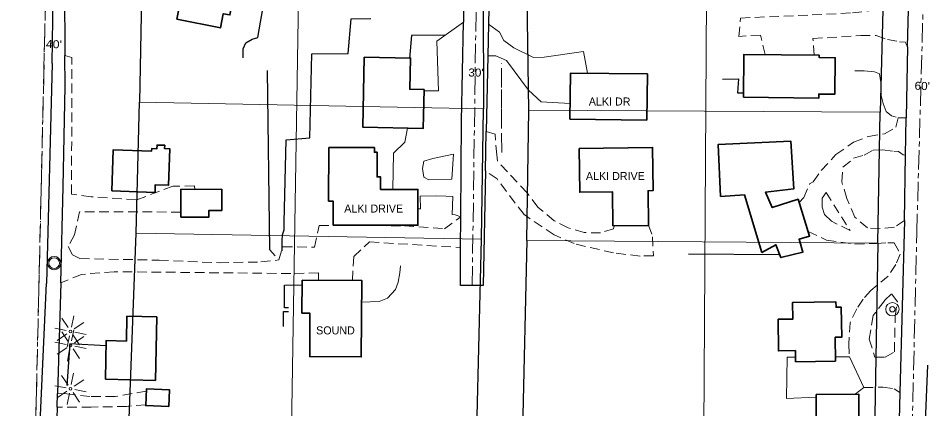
# Model space of a CAD drawing. Extents: x -861682 to -858969, y -1797841 to -1795153.
# Drawn here: x -861677 to -860995, y -1797216 to -1796923 of the extents above; entities that cross this region are included whole.
import ezdxf

# ---------------------------------------------------------------- set-up
doc = ezdxf.new("R2010")
doc.units = 0
doc.header["$LTSCALE"] = 2.4
for name, pattern in [('DOT_DASHED', [7.7, 5, -1.2, 0.3, -1.2]), ('LONG_DASH_SHORT_DASH', [9.9, 6, -1.2, 1.5, -1.2]), ('LONG_DASHED', [7.5, 6, -1.5]), ('MEDIUM_DASHED', [4.5, 3, -1.5])]:
    doc.linetypes.add(name, pattern=pattern)
for name, color, linetype, lineweight in [('10', 7, 'Continuous', 25), ('11', 7, 'Continuous', 13), ('12', 7, 'Continuous', 35), ('14', 7, 'Continuous', 25), ('17', 7, 'Continuous', 13), ('30', 7, 'Continuous', 13), ('31', 7, 'Continuous', 13), ('32', 7, 'LONG_DASH_SHORT_DASH', 13), ('36', 7, 'Continuous', 13), ('42', 7, 'Continuous', 25), ('46', 7, 'Continuous', 13), ('52', 7, 'LONG_DASHED', 13), ('61', 7, 'Continuous', 13)]:
    doc.layers.add(name, color=color, linetype=linetype, lineweight=lineweight)
doc.layers.add('43', color=7, linetype='Continuous')

msp = doc.modelspace()

# ---------------------------------------------------------------- linework, layer by layer
at = {"layer": '10'}
for p, q in [((-861010.143, -1796944.779), (-861009.05, -1796903.728)), ((-861323.862, -1796916.281), (-861324.107, -1796927.841)), ((-861010.143, -1796944.779), (-861010.99, -1796997.92)), ((-861011.439, -1797026.06), (-861010.99, -1796997.92)), ((-861326.432, -1797037.668), (-861325.808, -1797008.224)), ((-861012.218, -1797074.91), (-861011.439, -1797026.06)), ((-861345.039, -1797095.137), (-861344.865, -1797072)), ((-861012.218, -1797074.91), (-861015.76, -1797203.66)), ((-861644.853, -1797121.521), (-861647.128, -1797204.461)), ((-860998.692, -1797277.689), (-860994.825, -1797183.063)), ((-861647.407, -1797214.598), (-861647.128, -1797204.461)), ((-861647.407, -1797214.598), (-861649.011, -1797273.028))]:
    msp.add_line(p, q, dxfattribs=at)
for points in [[(-861342.201, -1796882.821), (-861342.913, -1796922.043), (-861342.989, -1796926.297)], [(-861641.79, -1796888.674), (-861642.058, -1796901.266), (-861641.695, -1796951.331)], [(-861344.865, -1797072), (-861344.329, -1797000.201), (-861342.989, -1796926.297)], [(-861324.107, -1796927.841), (-861324.612, -1796951.71), (-861325.808, -1797008.224)], [(-861644.853, -1797121.521), (-861642.88, -1797049.578), (-861641.529, -1796974.238), (-861641.695, -1796951.331)], [(-861326.432, -1797037.668), (-861328.248, -1797123.413), (-861345.252, -1797123.481), (-861345.039, -1797095.137)], [(-861015.76, -1797203.66), (-861017.164, -1797254.647), (-861017.272, -1797257.025)]]:
    msp.add_lwpolyline(points, dxfattribs=at)
at = {"layer": '11'}
for p, q in [((-861063.645, -1797177.024), (-861053.617, -1797176.953)), ((-861042.889, -1797199.962), (-861053.617, -1797176.953)), ((-861049.334, -1797204.944), (-861042.889, -1797199.962))]:
    msp.add_line(p, q, dxfattribs=at)
at = {"layer": '11', "linetype": 'MEDIUM_DASHED'}
for points in [[(-861116.694, -1796950.677), (-861120.23, -1796936.01), (-861136.522, -1796937.02), (-861135.16, -1796923.317), (-861081.56, -1796920.977), (-861051.337, -1796919.439), (-861031.509, -1796916.998), (-861019.483, -1796912.462), (-861011.719, -1796905.11), (-861009.05, -1796903.728)], [(-861079.929, -1796951.135), (-861081.017, -1796938.687), (-861045.129, -1796936.418), (-861033.557, -1796936.371), (-861025.043, -1796939.407), (-861016.062, -1796941.025), (-861011.809, -1796941.479), (-861010.143, -1796944.779)], [(-861544.283, -1797051.544), (-861544.638, -1797048.949), (-861560.696, -1797049.249), (-861588.286, -1797059.515), (-861622.067, -1797057.052), (-861636.717, -1797055.222), (-861636.419, -1796952.963), (-861641.695, -1796951.331)], [(-861091.353, -1797061.34), (-861087.859, -1797057.738), (-861083.414, -1797047.329), (-861080.822, -1797045.902), (-861074.716, -1797037.375), (-861063.664, -1797025.523), (-861050.476, -1797016.26), (-861039.394, -1797011.965), (-861027.357, -1797010.028), (-861018.875, -1797005.034), (-861017.014, -1796997.942), (-861010.99, -1796997.92)], [(-861229.902, -1797078.821), (-861230.409, -1797080.981), (-861240.079, -1797084.09), (-861252.36, -1797083.903), (-861264.419, -1797080.41), (-861274.832, -1797075.02), (-861287.153, -1797064.915), (-861295.226, -1797054.084), (-861317.284, -1797030.557), (-861318.013, -1797025.601), (-861319.255, -1797010.255), (-861325.808, -1797008.224)], [(-861012.218, -1797074.91), (-861019.755, -1797079.9), (-861030.615, -1797080.888), (-861040.063, -1797080.454), (-861049.541, -1797072.462), (-861055.502, -1797058.316), (-861059.331, -1797045.815), (-861058.43, -1797034.948), (-861050.427, -1797028.303), (-861042.643, -1797025.911), (-861035.809, -1797022.341), (-861028.489, -1797022.075), (-861020.219, -1797022.987), (-861016.913, -1797023.21), (-861013.36, -1797025.794), (-861011.439, -1797026.06)], [(-861204.222, -1797078.316), (-861201.1, -1797087.004), (-861200.57, -1797101.408), (-861210.489, -1797101.447), (-861230.336, -1797099.165), (-861259.885, -1797092.2), (-861275.025, -1797085.648), (-861297.523, -1797070.389), (-861317.704, -1797043.784), (-861326.432, -1797037.668)], [(-861554.714, -1797068.522), (-861630.76, -1797068.423), (-861634.469, -1797085.678), (-861639.157, -1797094.434), (-861636.063, -1797100.562), (-861630.384, -1797103.373), (-861571.102, -1797104.552), (-861525.986, -1797106.496), (-861494.815, -1797105.898), (-861481.359, -1797104.427), (-861478.329, -1797094.496), (-861454.475, -1797094.873), (-861450.998, -1797078.564), (-861387.232, -1797078.779), (-861357.23, -1797081.02), (-861344.865, -1797072)], [(-861084.575, -1797083.06), (-861070.728, -1797089.551), (-861049.461, -1797092.536), (-861033.404, -1797092), (-861024.904, -1797091.493), (-861019.945, -1797091.473), (-861015.424, -1797099.957), (-861018.699, -1797107.763), (-861024.568, -1797116.524), (-861037.514, -1797127.204), (-861043.391, -1797133.84), (-861048.086, -1797140.943), (-861053.004, -1797151.354), (-861054.12, -1797167.417), (-861053.617, -1797176.953)], [(-861426.134, -1797119.717), (-861425.163, -1797101.84), (-861413.398, -1797090.93), (-861345.039, -1797095.137)], [(-861451.478, -1797119.55), (-861451.564, -1797113.99), (-861472.344, -1797114.546), (-861604.839, -1797113.19), (-861629.155, -1797115.176), (-861644.853, -1797121.521)], [(-861042.889, -1797199.962), (-861028.485, -1797199.668), (-861019.978, -1797200.815), (-861015.76, -1797203.66)], [(-861580.652, -1797202.613), (-861603.991, -1797206.706), (-861622.885, -1797206.546), (-861640.132, -1797204.726), (-861647.128, -1797204.461)], [(-861581.028, -1797212.742), (-861595.224, -1797213.992), (-861621.908, -1797214.572), (-861647.407, -1797214.598)]]:
    msp.add_lwpolyline(points, dxfattribs=at)
at = {"layer": '11'}
for points in [[(-861372.503, -1796977.879), (-861361.659, -1796977.836), (-861362.753, -1796940.526), (-861342.989, -1796926.297)], [(-861249.861, -1796964.618), (-861252.905, -1796948.35), (-861282.408, -1796952.72), (-861290.437, -1796952.752), (-861305.108, -1796945.726), (-861312.688, -1796940.089), (-861316.019, -1796933.962), (-861324.107, -1796927.841)], [(-861262.947, -1796987.215), (-861284.636, -1796986.027), (-861294.117, -1796977.327), (-861310.738, -1796955.196), (-861318.546, -1796951.685), (-861324.612, -1796951.71)], [(-861384.884, -1797005.756), (-861386.774, -1797016.194), (-861395.479, -1797024.494), (-861395.981, -1797051.553)], [(-861377.058, -1797066.221), (-861375.238, -1797066.214), (-861375.277, -1797056.532), (-861363.233, -1797056.483), (-861355.911, -1797056.69), (-861350.95, -1797056.907), (-861351.369, -1797070.37), (-861349.242, -1797070.597), (-861344.865, -1797072)], [(-861094.016, -1797177.239), (-861100.368, -1797177.284), (-861100.716, -1797208.223), (-861078.52, -1797206.998)]]:
    msp.add_lwpolyline(points, dxfattribs=at)
msp.add_lwpolyline([(-861350.369, -1797025.259), (-861365.943, -1797028.391), (-861372.547, -1797030.543), (-861373.706, -1797035.98), (-861372.736, -1797042.352), (-861368.949, -1797044.462), (-861351.711, -1797043.921)], close=True, dxfattribs=at)
at = {"layer": '11', "linetype": 'MEDIUM_DASHED'}
for points in [[(-861067.006, -1797075.366), (-861072.221, -1797070.427), (-861073.897, -1797064.766), (-861073.923, -1797058.153), (-861071.106, -1797053.891), (-861053.044, -1797082.395)], [(-861027.327, -1797134.955), (-861035.784, -1797146.089), (-861038.784, -1797163.577), (-861034.479, -1797177.257), (-861026.685, -1797177.226), (-861019.853, -1797173.184), (-861019.25, -1797146.731), (-861017.641, -1797135.861), (-861022.152, -1797129.739)]]:
    msp.add_lwpolyline(points, close=True, dxfattribs=at)
at = {"layer": '12'}
for points in [[(-861557.655, -1796924.07), (-861525.038, -1796930.551), (-861522.953, -1796920.056), (-861518.03, -1796921.034), (-861514.896, -1796905.256), (-861518.03, -1796904.633), (-861515.701, -1796892.917), (-861534.817, -1796889.117), (-861535.959, -1796894.86), (-861541.116, -1796893.835), (-861542.194, -1796899.257), (-861546.355, -1796898.43), (-861549.481, -1796914.158), (-861555.449, -1796912.972)], [(-861417.258, -1796952.551), (-861418.464, -1797004.984), (-861373.15, -1797006.026), (-861372.481, -1796976.921), (-861383.145, -1796976.676), (-861382.609, -1796953.347)], [(-861133.031, -1796982.582), (-861076.586, -1796983.302), (-861076.547, -1796980.229), (-861064.557, -1796980.381), (-861064.21, -1796953.023), (-861076.231, -1796952.871), (-861076.21, -1796951.181), (-861132.632, -1796950.479)], [(-861263.092, -1796998.927), (-861205.465, -1796999.641), (-861205.038, -1796965.173), (-861262.665, -1796964.459)], [(-861119.339, -1797098.718), (-861132.265, -1797055.552), (-861150.209, -1797056.805), (-861152.017, -1797018.082), (-861097.474, -1797015.501), (-861095.205, -1797051.153), (-861116.45, -1797053.6), (-861111.445, -1797065.152), (-861092.104, -1797058.934), (-861083.492, -1797086.53), (-861091.275, -1797088.923), (-861088.403, -1797098.594), (-861104.918, -1797102.675), (-861108.735, -1797093.008)], [(-861606.497, -1797052.738), (-861574.139, -1797053.789), (-861573.955, -1797048.128), (-861564.018, -1797048.451), (-861563.132, -1797021.19), (-861566.945, -1797021.066), (-861566.864, -1797018.575), (-861572.619, -1797018.388), (-861572.71, -1797021.189), (-861576.626, -1797021.062), (-861576.685, -1797022.868), (-861605.491, -1797021.927)], [(-861443.909, -1797020.201), (-861443.984, -1797060.349), (-861440.678, -1797060.355), (-861440.711, -1797078.287), (-861377.081, -1797078.404), (-861377.032, -1797051.588), (-861405.056, -1797051.537), (-861405.039, -1797042.242), (-861407.688, -1797042.237), (-861407.653, -1797023.834), (-861409.651, -1797023.83), (-861409.643, -1797020.274)], [(-861256.154, -1797020.861), (-861201.131, -1797020.168), (-861200.724, -1797052.507), (-861204.546, -1797052.555), (-861204.22, -1797078.499), (-861230.885, -1797078.834), (-861231.205, -1797053.348), (-861255.742, -1797053.656)], [(-861554.698, -1797072.367), (-861533.68, -1797072.283), (-861533.7, -1797067.324), (-861524.018, -1797067.285), (-861524.082, -1797051.462), (-861554.782, -1797051.586)], [(-861463.821, -1797119.469), (-861419.185, -1797119.763), (-861419.561, -1797176.924), (-861458.176, -1797176.67), (-861457.963, -1797144.246), (-861463.983, -1797144.207)], [(-861063.986, -1797180.207), (-861093.977, -1797180.564), (-861094.075, -1797172.295), (-861106.765, -1797172.445), (-861107.045, -1797148.737), (-861095.993, -1797148.606), (-861096.14, -1797136.174), (-861063.69, -1797135.79), (-861063.642, -1797139.822), (-861059.661, -1797139.775), (-861059.396, -1797162.235), (-861064.199, -1797162.292)], [(-861611.363, -1797193.745), (-861573.81, -1797194.539), (-861572.806, -1797147.072), (-861595.237, -1797146.598), (-861595.628, -1797165.113), (-861610.752, -1797164.794)], [(-861563.813, -1797214.101), (-861581.055, -1797213.461), (-861580.591, -1797200.957), (-861563.349, -1797201.597)], [(-861078.528, -1797205.062), (-861046.411, -1797204.933), (-861046.275, -1797238.704), (-861078.392, -1797238.834)]]:
    msp.add_lwpolyline(points, close=True, dxfattribs=at)
at = {"layer": '14'}
msp.add_line((-861174.125, -1797099.883), (-861106.581, -1797100.321), dxfattribs=at)
for points in [[(-861507.944, -1796953.155), (-861507.972, -1796946.307), (-861506.101, -1796941.812), (-861501.388, -1796939.196), (-861497.143, -1796937.762), (-861488.6, -1796889.078), (-861485.53, -1796889.066), (-861483.64, -1796889.058)], [(-861478.789, -1797097.568), (-861478.79, -1797097.332), (-861478.819, -1797090.011), (-861478.601, -1797085.523), (-861477.435, -1797081.976), (-861477.222, -1797076.071), (-861475.816, -1797014.428), (-861458.11, -1797012.94), (-861456.472, -1796950.114), (-861429.315, -1796949.768), (-861427.057, -1796923.782), (-861412.415, -1796923.723)], [(-861356.866, -1796936.252), (-861381.899, -1796936.352), (-861383.483, -1796953.599)], [(-861483.969, -1797101.368), (-861488.002, -1797096.897), (-861489.722, -1796962.528)], [(-861148.673, -1796968.949), (-861136.629, -1796968.901), (-861137.532, -1796979.295), (-861132.989, -1796979.234)], [(-861474.13, -1797140.294), (-861476.964, -1797140.306), (-861477.032, -1797123.302), (-861463.844, -1797122.931)], [(-861477.853, -1797154.243), (-861477.898, -1797142.907), (-861474.12, -1797142.892)], [(-861610.835, -1797168.745), (-861637.921, -1797167.167), (-861640.158, -1797198.349)]]:
    msp.add_lwpolyline(points, dxfattribs=at)
at = {"layer": '17'}
for p, q in [((-861639.285, -1797155.055), (-861644.075, -1797147.927)), ((-861636.825, -1797154.595), (-861635.099, -1797146.195)), ((-861634.625, -1797155.995), (-861627.529, -1797151.255)), ((-861640.785, -1797157.255), (-861649.247, -1797155.581)), ((-861639.244, -1797165.446), (-861644.034, -1797158.318)), ((-861636.784, -1797164.986), (-861635.058, -1797156.586)), ((-861634.185, -1797158.515), (-861625.705, -1797160.239)), ((-861640.744, -1797167.646), (-861649.206, -1797165.972)), ((-861640.245, -1797159.755), (-861647.471, -1797164.611)), ((-861639.865, -1797169.715), (-861638.185, -1797161.115)), ((-861635.525, -1797160.655), (-861630.725, -1797167.869)), ((-861634.584, -1797166.386), (-861627.488, -1797161.646)), ((-861640.204, -1797170.146), (-861647.43, -1797175.002)), ((-861639.824, -1797180.106), (-861638.144, -1797171.506)), ((-861635.484, -1797171.046), (-861630.684, -1797178.26)), ((-861634.144, -1797168.906), (-861625.664, -1797170.63)), ((-861639.349, -1797198.037), (-861644.139, -1797190.909)), ((-861636.889, -1797197.577), (-861635.163, -1797189.177)), ((-861640.849, -1797200.237), (-861649.311, -1797198.563)), ((-861634.689, -1797198.977), (-861627.593, -1797194.237)), ((-861640.309, -1797202.737), (-861647.535, -1797207.593)), ((-861639.929, -1797212.697), (-861638.249, -1797204.097)), ((-861635.589, -1797203.637), (-861630.789, -1797210.851)), ((-861634.249, -1797201.497), (-861625.769, -1797203.221))]:
    msp.add_line(p, q, dxfattribs=at)
for centre in [(-861637.485, -1797157.955), (-861637.444, -1797168.346), (-861637.549, -1797200.937)]:
    msp.add_circle(centre, 1, dxfattribs=at)
at = {"layer": '30'}
for p, q in [((-861163.628, -1797374.823), (-861160.072, -1796802.305)), ((-861465.508, -1796850.044), (-861480.985, -1797800.155)), ((-861327.8, -1796991.251), (-861585.789, -1796986.257)), ((-861293.837, -1796992.387), (-861030.52, -1796993.813)), ((-861329.456, -1797088.773), (-861588.243, -1797084.303)), ((-861295.45, -1797089.904), (-861032.296, -1797091.766))]:
    msp.add_line(p, q, dxfattribs=at)
at = {"layer": '31'}
for radius in [5, 2]:
    msp.add_circle((-861021.398, -1797141.308), radius, dxfattribs=at)
at = {"layer": '32'}
for points in [[(-861016.908, -1797697.112), (-861016.908, -1797629.868), (-861015.071, -1797572.938), (-861015.071, -1797447.139), (-861012.317, -1797374.599), (-861007.726, -1797281.857), (-861003.087, -1797084.148), (-860992.207, -1796696.344), (-860992.984, -1796576.661), (-860989.487, -1796449.983), (-860987.933, -1796343.901), (-860987.544, -1796199.737), (-860984.047, -1796080.831), (-860987.933, -1795887.705), (-860991.735, -1795769.455)], [(-861635.972, -1796031.868), (-861668.34, -1797434.932), (-861671.877, -1797797.365)], [(-861336.345, -1797123.445), (-861333.081, -1796888.015), (-861331.83, -1796872.168), (-861327.659, -1796856.738), (-861321.821, -1796845.478), (-861312.646, -1796834.219), (-861305.557, -1796827.129), (-861293.463, -1796820.457), (-861279.702, -1796815.453), (-861249.874, -1796808.735), (-861088.25, -1796770.144), (-860993.655, -1796747.958)]]:
    msp.add_lwpolyline(points, dxfattribs=at)
at = {"layer": '36'}
for radius in [5, 4]:
    msp.add_circle((-861649.735, -1797106.757), radius, dxfattribs=at)
at = {"layer": '42'}
for p, q in [((-861651.202, -1796957.407), (-861647.476, -1796719.081)), ((-861328.727, -1796817.832), (-861327.8, -1796991.251)), ((-861583.726, -1796880.798), (-861585.789, -1796986.257)), ((-861651.202, -1796957.407), (-861655.483, -1797122.019)), ((-861588.243, -1797084.303), (-861585.789, -1796986.257)), ((-861329.456, -1797088.773), (-861327.8, -1796991.251)), ((-861295.45, -1797089.904), (-861293.837, -1796992.387)), ((-861032.296, -1797091.766), (-861030.52, -1796993.813)), ((-861593.747, -1797229.638), (-861588.243, -1797084.303)), ((-861332.881, -1797234.296), (-861329.456, -1797088.773)), ((-861295.45, -1797089.904), (-861298.67, -1797233.588)), ((-861662.023, -1797266.955), (-861655.483, -1797122.019))]:
    msp.add_line(p, q, dxfattribs=at)
for points in [[(-861293.837, -1796992.387), (-861296.182, -1796840.974), (-861024.656, -1796763.832), (-861030.52, -1796993.813)], [(-861032.296, -1797091.766), (-861034.85, -1797234.814), (-861037.376, -1797375.712)]]:
    msp.add_lwpolyline(points, dxfattribs=at)
at = {"layer": '52'}
for points in [[(-861314.241, -1797023.932), (-861314.372, -1796991.106), (-861314.436, -1796975.284), (-861314.509, -1796957.1)], [(-861018.669, -1796997.476), (-861021.979, -1796996.545), (-861026.007, -1796993.254), (-861028.392, -1796987.36), (-861029.834, -1796981.226), (-861030.109, -1796971.544), (-861031.079, -1796965.172), (-861034.864, -1796963.534), (-861042.424, -1796962.856), (-861049.509, -1796962.884)], [(-861419.292, -1797136.103), (-861406.134, -1797135.535), (-861399.768, -1797132.911), (-861393.89, -1797126.511), (-861391.786, -1797121.071), (-861390.634, -1797113.982), (-861390.182, -1797108.784)]]:
    msp.add_lwpolyline(points, dxfattribs=at)
at = {"layer": '61', "linetype": 'DOT_DASHED'}
msp.add_line((-861615.801, -1795157.51), (-861676.699, -1797797.295), dxfattribs=at)

# ---------------------------------------------------------------- texts
at = {"layer": '43'}
for s, rotation, width, p in [("40'", 358.633, 1.15, (-861656.023, -1796945.727)), ("30'", 359.193, 1.1, (-861339.335, -1796967.041)), ("60'", 358.37, 1.1, (-861004.852, -1796976.953))]:
    msp.add_text(s, height=6, rotation=rotation, dxfattribs=dict(at, width=width)).set_placement(p)
at = {"layer": '46'}
for s, p in [('ALKI DR', (-861248.949, -1796988.788)), ('ALKI DRIVE', (-861251.128, -1797044.571)), ('ALKI DRIVE', (-861432.295, -1797068.896)), ('SOUND', (-861453.347, -1797160.124))]:
    msp.add_text(s, height=6, dxfattribs=at).set_placement(p)

doc.saveas('drawing.dxf')
